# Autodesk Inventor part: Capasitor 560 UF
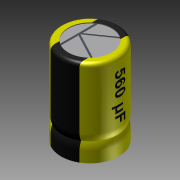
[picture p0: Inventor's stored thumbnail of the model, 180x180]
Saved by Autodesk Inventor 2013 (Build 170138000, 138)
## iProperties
Company: Autodesk Inc.
Created: 2005-12
Part Number: Capasitor 560 UF
Document SubType Name: Modeling
Designer: Autodesk Inc.
Density: 1 g/cm^3
Mass: 0.595411 g
Surface Area: 4.02698 cm^2
Volume: 0.595411 cm^3
Material: Allgemein
Title: Personal Computer
Author: Autodesk Inc.
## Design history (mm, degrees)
sketch "Sketch1"
  geometry: L1 (0, 5.6)-(0, -5.6) reference; L2 (-5.6, 0)-(5.6, 0) reference; C1 r 4 at (0, 0)
  constraints: 2 midpoint, 1 centre point
  dimensions: "d0" = 8 diameter of C1
extrude "Extrusion1" new body sketch "Sketch1" distance "d1" = 12; taper "d2" = 0 deg
revolve "Revolution1" stored, may be unused: angle "d19" = 90 deg
sketch "Sketch2"
  geometry: C1 r 4 at (0, 0) reference; C2 r 3 at (0, 0)
  constraints: 1 centre point, 1 coincident
  dimensions: "d3" = 1 radial gap between concentric circles of C2 C1
extrude "Extrusion2" cut sketch "Sketch2" distance "d4" = 0.1; taper "d5" = 0 deg
sketch "Sketch3"
  geometry: L1 (-1.735, 2.896)-(-1.471, 2.896); L2 (-1.471, 2.896)-(-1.471, -3.053); L3 (-1.471, -3.053)-(-1.735, -3.053); L4 (-1.735, -3.053)-(-1.735, 2.896); L5 (-1.471, 0.123)-(-1.596, 0.302); L6 (-1.596, 0.302)-(1.797, 2.672); L7 (1.797, 2.672)-(1.922, 2.493); L8 (1.922, 2.493)-(-1.471, 0.123); L9 (-1.471, 0.123)-(-1.578, -0.079); L10 (-1.578, -0.079)-(2.364, -2.162); L11 (2.364, -2.162)-(2.47, -1.96); L12 (2.47, -1.96)-(-1.471, 0.123)
  constraints: 24 end point, 6 parallel, 3 perpendicular, 1 horizontal, 1 point on line
extrude "Extrusion3" cut sketch "Sketch3" distance "d6" = 0.05; taper "d7" = 0 deg
fillet "Fillet1" dims "d8" = 0.5
sketch "Sketch5"
  geometry: L1 (2, -2.236)-(2, -5); L2 (2, -5)-(-2, -5); L3 (-2, -5)-(-2, -2.236); L4 (0, -6.8)-(0, 5.8) reference; A1 r 3 centre (0, 0) between (-2, -2.236) and (2, -2.236) reference; 3 further points
  constraints: 6 end point, 2 point on circle, 1 coincident, 1 parallel, 1 point on line, 1 vertical alignment, 2 other
  dimensions: "d12" = 1 distance from line of L2 point (0, -4); "d13" = 4 distance of L1.end L2.end
split "Split1" sketch "Sketch5"
workplane "Work Plane1"
sketch "Sketch4"
  geometry: L1 (-10.475, 1.043)-(5.133, 1.043); L2 (5.133, 1.043)-(5.133, -2.796); L3 (5.133, -2.796)-(-10.475, -2.796); L4 (-10.475, -2.796)-(-10.475, 1.043)
  constraints: 2 other
emboss "Emboss1" sketch "Sketch4" dims "d10" = 0.05, "d11" = 0
body "Solid1"
sketch "Sketch6"
  geometry: L1 (0, 14.4)-(0, -2.4) reference; L2 (4, 0)-(4, 12) reference; L3 (4, 3.5)-(4, 1.5); L4 (4, 2.5)-(3.8, 2.5); L5 (-4, 0)-(4, 0) reference; A1 r 2.6 centre (1.4, 3.5) between (3.8, 2.5) and (4, 3.5); A2 r 2.6 centre (1.4, 1.5) between (4, 1.5) and (3.8, 2.5); 1 further point
  constraints: 4 end point, 4 point on circle, 2 centre point, 2 point on line, 2 tangent, 1 collinear, 1 horizontal, 1 midpoint
  dimensions: "d16" = 2 distance of L3.start L3.end; "d17" = 2.5 distance between parallel lines of L5 L4; "d18" = 0.2 distance of L4.start L4.end
